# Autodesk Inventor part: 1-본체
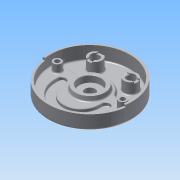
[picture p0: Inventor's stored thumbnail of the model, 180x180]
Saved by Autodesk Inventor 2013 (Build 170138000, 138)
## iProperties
Created: 2015-06
Part Number: 1-본체
Material: 알루미늄 6061
Document SubType Name: Modeling
Designer: Administrator
Density: 1 g/cm^3
Author: Administrator
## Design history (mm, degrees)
sketch "스케치1"
  geometry: C1 r 95 at (0, 0); 1 further point
  constraints: 1 centre point, 1 coincident
  dimensions: "d0" = 190 diameter of C1
extrude "돌출1" new body sketch "스케치1" distance "d2" = 32; taper "d3" = 0 deg
feature "쉘1" dims "d4" = 14, "d5" = 5
sketch "스케치2"
  geometry: C1 r 90 at (0, 0) reference; C2 r 35 at (0, 0)
  constraints: 1 centre point, 1 coincident
  dimensions: "d6" = 70 diameter of C2
extrude "돌출2" join sketch "스케치2" distance "d8" = 10; taper "d9" = -10 deg
sketch "스케치3"
  geometry: L1 (45.033, 16)-(75.657, 16); L2 (-45.033, 16)-(-75.657, 16); C1 r 35 at (0, 0) reference; C2 r 90 at (0, 0) reference; A1 r 42 centre (0, 0) between (36.373, 21) and (-36.373, 21); A2 r 10 centre (-75.657, 26) between (-85.114, 29.25) and (-75.657, 16); A3 r 10 centre (75.657, 26) between (75.657, 16) and (85.114, 29.25); A4 r 90 centre (0, 0) between (-85.114, 29.25) and (85.114, 29.25) reference; A5 r 10 centre (-45.033, 26) between (-45.033, 16) and (-36.373, 21); A6 r 10 centre (45.033, 26) between (36.373, 21) and (45.033, 16)
  constraints: 12 point on circle, 8 tangent, 5 centre point, 4 end point, 2 collinear, 2 equal radius, 1 coincident, 1 horizontal
  dimensions: "d10" = 84 diameter of A1; "d12" = 16 distance from line of L1 C1.centre; "d13" = 10 radius of A2; "d14" = 10 radius of A5
extrude "돌출3" cut sketch "스케치3" distance "d15" = 7; taper "d16" = 0 deg
sketch "스케치4"
  geometry: L1 (-59, -19)-(-59, -14); L2 (-41, -19)-(-41, -14); L3 (41, -19)-(41, -14); L4 (59, -19)-(59, -14); A1 r 90 centre (0, 0) between (-85.114, 29.25) and (85.114, 29.25) reference; A2 r 9 centre (-50, -19) between (-59, -19) and (-41, -19); A3 r 9 centre (50, -19) between (59, -19) and (41, -19); A4 r 41 centre (0, -19) between (-41, -19) and (41, -19); A5 r 9 centre (-50, -14) between (-59, -14) and (-41, -14); A6 r 9 centre (50, -14) between (41, -14) and (59, -14); A7 r 59 centre (0, -19) between (-59, -19) and (59, -19)
  constraints: 12 point on circle, 9 tangent, 8 end point, 6 centre point, 3 equal radius, 3 vertical alignment, 2 horizontal alignment, 1 coincident
  dimensions: "d36" = 19 distance of A7.centre A1.centre; "d38" = 41 radius of A4; "d39" = 5 distance of A2.centre A5.centre; "d40" = 59 radius of A7
extrude "돌출4" cut sketch "스케치4" distance "d21" = 7; taper "d22" = 0 deg
sketch "스케치5"
  geometry: L1 (-45.033, 16)-(-75.657, 16) reference; L2 (-74, 0)-(74, 0); C1 r 9 at (-74, 0); C2 r 9 at (74, 0); A1 r 90 centre (0, 0) between (-85.114, 29.25) and (85.114, 29.25) reference; 1 further point
  constraints: 2 centre point, 2 end point, 2 horizontal alignment, 1 coincident, 1 equal radius, 1 midpoint, 1 parallel
  dimensions: "d23" = 18 diameter of C1; "d25" = 148 distance of L2.end L2.start
extrude "돌출5" join sketch "스케치5" stored distance "d26" = 7; taper "d27" = 0 deg
sketch "스케치6"
  geometry: L1 (-45.033, 16)-(-75.657, 16) reference; L2 (-40, 52)-(40, 52); C1 r 15 at (-40, 52); C2 r 15 at (40, 52); C3 r 10 at (-40, 52); C4 r 10 at (40, 52); A1 r 90 centre (0, 0) between (85.114, 29.25) and (-85.114, 29.25) reference; 1 further point
  constraints: 4 centre point, 2 coincident, 2 end point, 2 equal radius, 1 horizontal alignment, 1 midpoint, 1 parallel, 1 vertical alignment
  dimensions: "d28" = 30 diameter of C1; "d30" = 52 vertical distance of L2.end A1.centre; "d31" = 80 distance of L2.end L2.start; "d32" = 20 diameter of C3
extrude "돌출6" join sketch "스케치6" stored distance "d33" = 0; taper "d34" = 0 deg
sketch "스케치7"
  geometry: C1 r 9 at (-74, 0) reference; C2 r 9 at (74, 0) reference; 2 further points
  constraints: 2 coincident
hole "구멍1" sketch "스케치7" at (-74, 0), (74, 0) diameter "d41" = 11; stored, may be unused: countersink angle "d45" = 90 deg, drill point angle "d47" = 118 deg; dims "d42" = 6, "d43" = 18, "d44" = 11, "d46" = 8
hole "구멍2" diameter "d50" = 23; stored, may be unused: countersink angle "d54" = 90 deg, drill point angle "d56" = 118 deg; dims "d48" = 10, "d49" = 10, "d51" = 6, "d52" = 50, "d53" = 15, "d55" = 8
extrude "돌출7" cut sketch "스케치6" stored distance "d57" = 7; taper "d58" = 0 deg
sketch "스케치8"
  geometry: L1 (-89.124, -12.526)-(-94.075, -13.221); L2 (89.124, -12.526)-(94.075, -13.221); L3 (-95, 0)-(95, 0); A1 r 90 centre (0, 0) between (-89.124, -12.526) and (89.124, -12.526) reference; A2 r 95 centre (0, 0) between (-94.075, -13.221) and (94.075, -13.221) reference
  constraints: 6 end point, 6 point on circle, 1 horizontal, 1 horizontal alignment, 1 midpoint
  dimensions: "d59" = 8 deg angle of L3 L1; "d60" = 8 deg angle of L3 L2; "d61" = 13.22144 vertical distance of L3.start L1.end
extrude "돌출8" join sketch "스케치8" distance "d62" = 5; taper "d63" = 0 deg
sketch "스케치9"
  geometry: C1 r 95 at (0, 0) reference; C2 r 68 at (0, 0)
  constraints: 1 centre point, 1 coincident, 1 other
  dimensions: "d64" = 136 diameter of C2
feature "엠보싱1" sketch "스케치9" dims "d10" = 84, "d12" = 16, "d13" = 10, "d14" = 10, "d66" = 0.5, "d67" = 0
chamfer "모따기1" distance "d68" = 1; stored, may be unused: second distance "d69" = 2, angle "d70" = 45 deg
sketch "스케치10"
  geometry: L1 (-6, 13.748)-(-6, -13.748); L2 (6, 13.748)-(6, -13.748); L3 (66.252, 6)-(93.748, 6); L4 (66.252, -6)-(93.748, -6); C1 r 10 at (80, 0) reference; A1 r 15 centre (0, 0) between (-6, 13.748) and (-6, -13.748) reference; A2 r 15 centre (80, 0) between (66.252, 6) and (93.748, 6) reference; 1 further point
  constraints: 8 end point, 8 point on circle, 4 parallel, 1 perpendicular, 1 vertical
  dimensions: "d71" = 12 distance between parallel lines of L2 L1; "d72" = 12 distance between parallel lines of L4 L3
extrude "돌출9" cut sketch "스케치10" distance "d73" = 3; taper "d74" = 0 deg
fillet "모깎기1" dims "d75" = 3
fillet "모깎기2" dims "d76" = 3
sketch "스케치11"
  geometry: C1 r 11.5 at (0, 0) reference; C2 r 26 at (0, 0)
  constraints: 1 centre point, 1 coincident
  dimensions: "d77" = 52 diameter of C2
extrude "돌출10" join sketch "스케치11" distance "d79" = 12; taper "d80" = -15 deg
fillet "모깎기3" dims "d81" = 5
hole "구멍3" diameter "d84" = 23; stored, may be unused: countersink angle "d88" = 90 deg, drill point angle "d90" = 118 deg; dims "d82" = 10, "d83" = 10, "d85" = 6, "d86" = 4, "d87" = 2, "d89" = 8
chamfer "모따기2" distance "d91" = 1; stored, may be unused: second distance "d92" = 2, angle "d93" = 45 deg
fillet "모깎기4" dims "d94" = 1
fillet "모깎기5" dims "d95" = 3
fillet "모깎기6" dims "d96" = 0.3
node "솔리드1"
other parameters: "d37" = 59
